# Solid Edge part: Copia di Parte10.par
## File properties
Author: f_grande
Template: Normal.par
Last saved by: f_grande
Revision: 1
Application: Solid Edge
Densità: 750,000 kg/m^3
Precisione: 0,990
Tipo di contenuto documento: 0
Material: MDF
Stile della faccia: Marroncino
Coef. of Thermal Exp: 0.0
Thermal Conductivity: 0.0
Specific Heat: 0.0
Modulus of Elasticity: 0.0
Poisson's Ratio: 0.0
Yield Stress: 0.0
Ultimate Stress: 0.0
Elongation: 0.0
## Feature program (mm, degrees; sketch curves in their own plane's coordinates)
sketch for "unnamed Protrusion 1" plane through (0, 0, 0) normal (0, -1, 0) x-axis (1, 0, 0)
  line (-62.5, 9.5) -> (62.5, 9.5)
  line (62.5, 9.5) -> (62.5, -9.5)
  line (62.5, -9.5) -> (-62.5, -9.5)
  line (-62.5, -9.5) -> (-62.5, 9.5)
  dimension (linear) = 62.5
  dimension (linear) = 62.5
extrude "unnamed Protrusion 1" add finite 120 along +normal
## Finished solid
Body 1: solid body, 6 faces, 12 edges, 8 vertices.
  Faces by surface: plane 6
  Edges by curve: line 12
Bounding box of the edges (mm): 125.000 x 120.000 x 19.000, from (-62.5, -120, -9.5) to (62.5, 0, 9.5).
Planar faces by outward normal: +x 1, +y 1, +z 1, -x 1, -y 1, -z 1
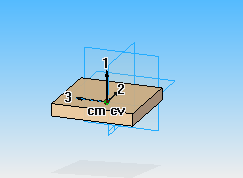
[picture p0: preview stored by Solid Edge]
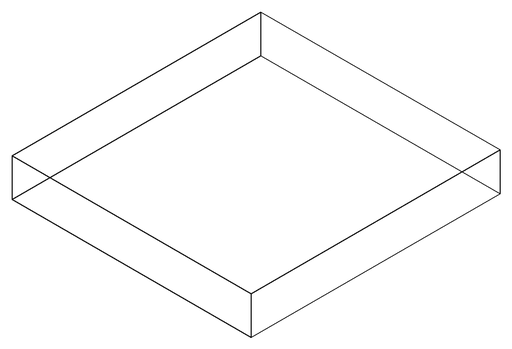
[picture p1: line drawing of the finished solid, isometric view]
